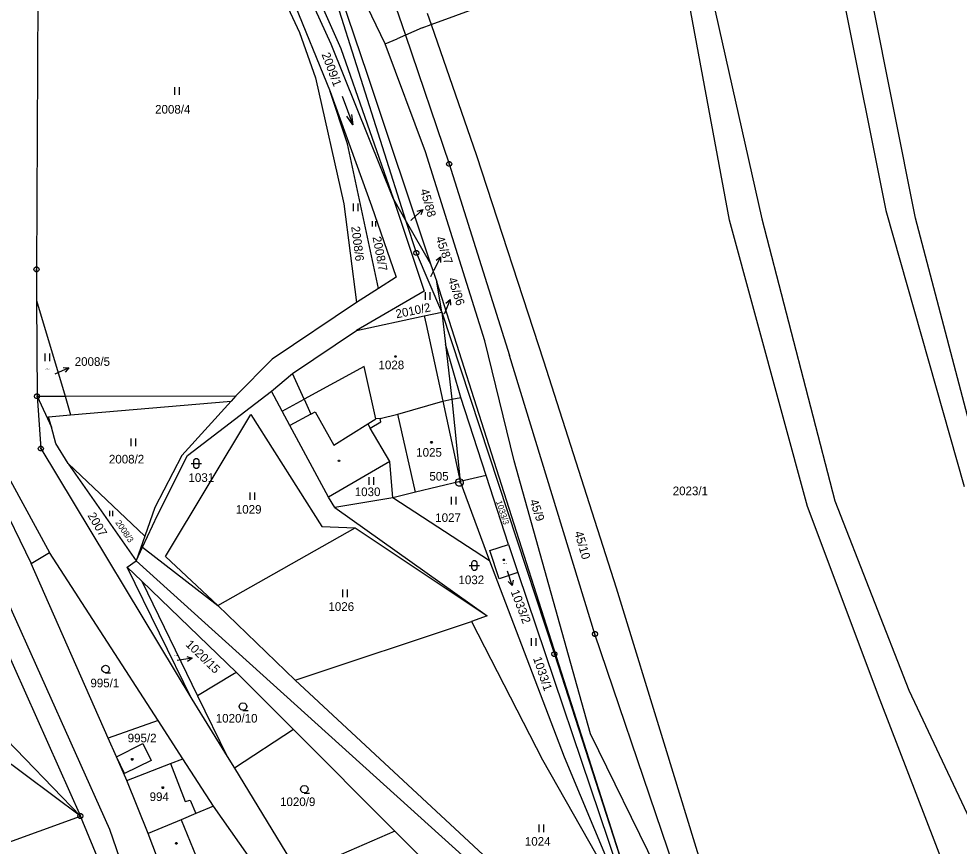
# Model space of a CAD drawing. Extents: x -609861 to -605046, y -1120287 to -1116307.
# Drawn here: x -607702.6 to -607517.4, y -1118558 to -1118395 of the extents above; entities that cross this region are included whole.
import ezdxf

# ---------------------------------------------------------------- set-up
doc = ezdxf.new("R2010")
doc.units = 0
for name, color, linetype in [('Vrstva 1', 7, 'Continuous'), ('Vrstva 2', 7, 'Continuous'), ('Vrstva 3', 7, 'Continuous'), ('Vrstva 4', 7, 'Continuous'), ('Vrstva 5', 7, 'Continuous'), ('Vrstva 7', 7, 'Continuous'), ('Vrstva 8', 7, 'Continuous')]:
    doc.layers.add(name, color=color, linetype=linetype)

msp = doc.modelspace()

# ---------------------------------------------------------------- linework, layer by layer
at = {"layer": 'Vrstva 1'}
for p, q in [((-607626.28, -1118434.95), (-607655.66, -1118342.38)), ((-607655.66, -1118342.38), (-607633.97, -1118405.89)), ((-607660.12, -1118370.59), (-607647.3, -1118397.68)), ((-607544.1, -1118371.59), (-607531.82, -1118432.76)), ((-607525.99, -1118434.27), (-607538.6, -1118370.99)), ((-607641.07, -1118400.03), (-607653.52, -1118372.62)), ((-607630.48, -1118399.97), (-607642.4, -1118375)), ((-607569.78, -1118374.03), (-607556.29, -1118434.42)), ((-607649.03, -1118378.53), (-607639.21, -1118400.88)), ((-607621.4, -1118396.15), (-607573.11, -1118378.35)), ((-607562.64, -1118434.7), (-607573.11, -1118378.35)), ((-607653.54, -1118379.09), (-607641.29, -1118409.31)), ((-607698.86, -1118390.68), (-607699.1, -1118444.38)), ((-607629.03, -1118390.71), (-607626.47, -1118398.24)), ((-607622.19, -1118393.87), (-607621.4, -1118396.15)), ((-607623.15, -1118396.79), (-607626.47, -1118398.24)), ((-607623.15, -1118396.79), (-607621.4, -1118396.15)), ((-607621.4, -1118396.15), (-607612.48, -1118421.94)), ((-607647.3, -1118397.68), (-607644.16, -1118406.63)), ((-607630.48, -1118399.97), (-607628.07, -1118398.93)), ((-607626.47, -1118398.24), (-607628.07, -1118398.93)), ((-607628.81, -1118430.54), (-607641.07, -1118400.03)), ((-607639.21, -1118400.88), (-607628.81, -1118430.54)), ((-607622.51, -1118421.25), (-607630.48, -1118399.97)), ((-607644.16, -1118406.63), (-607638.59, -1118431.48)), ((-607633.97, -1118405.89), (-607621.49, -1118443.27)), ((-607637.87, -1118419.62), (-607641.29, -1118409.31)), ((-607641.29, -1118409.31), (-607633.12, -1118431.84)), ((-607631.75, -1118448.12), (-607637.87, -1118419.62)), ((-607610.85, -1118458.43), (-607622.51, -1118421.25)), ((-607612.48, -1118421.94), (-607599.29, -1118462.39)), ((-607628.81, -1118430.54), (-607626.28, -1118434.95)), ((-607628.81, -1118430.54), (-607622.79, -1118448.7)), ((-607638.59, -1118431.48), (-607636.11, -1118450.91)), ((-607633.12, -1118431.84), (-607628.26, -1118445.89)), ((-607531.82, -1118432.76), (-607516.42, -1118487.17)), ((-607556.29, -1118434.42), (-607541.9, -1118490.01)), ((-607512.94, -1118484.15), (-607525.99, -1118434.27)), ((-607626.28, -1118434.95), (-607621.49, -1118443.27)), ((-607547.31, -1118491.11), (-607562.64, -1118434.7)), ((-607621.49, -1118443.27), (-607620.29, -1118446.85)), ((-607699.1, -1118444.38), (-607699.08, -1118450.52)), ((-607628.26, -1118445.89), (-607631.75, -1118448.12)), ((-607579.33, -1118575.18), (-607620.29, -1118446.85)), ((-607619.32, -1118452.8), (-607620.29, -1118446.85)), ((-607631.75, -1118448.12), (-607636.11, -1118450.91)), ((-607622.79, -1118448.7), (-607636.07, -1118456.39)), ((-607699.08, -1118450.52), (-607693.49, -1118469.37)), ((-607699.08, -1118450.52), (-607699, -1118469.38)), ((-607636.11, -1118450.91), (-607652.73, -1118462.05)), ((-607622.74, -1118453.54), (-607619.32, -1118452.8)), ((-607619.32, -1118452.8), (-607618.59, -1118459.11)), ((-607619.32, -1118452.8), (-607597.12, -1118520.18)), ((-607636.07, -1118456.39), (-607622.74, -1118453.54)), ((-607648.72, -1118464.87), (-607636.07, -1118456.39)), ((-607605.03, -1118482.13), (-607610.85, -1118458.43)), ((-607618.59, -1118459.11), (-607617.33, -1118469.97)), ((-607615.57, -1118469.61), (-607618.59, -1118459.11)), ((-607652.73, -1118462.05), (-607659.85, -1118469.32)), ((-607589.13, -1118516.23), (-607605.98, -1118461.36)), ((-607599.29, -1118462.39), (-607584.95, -1118507.14)), ((-607652.86, -1118468.36), (-607648.72, -1118464.87)), ((-607699, -1118469.38), (-607698.26, -1118479.69)), ((-607699, -1118469.38), (-607696.18, -1118475.47)), ((-607693.49, -1118469.37), (-607692.4, -1118473.07)), ((-607669.36, -1118481.06), (-607652.86, -1118468.36)), ((-607659.85, -1118469.32), (-607660.8, -1118470.36)), ((-607650.71, -1118472.33), (-607652.86, -1118468.36)), ((-607610.54, -1118485.02), (-607615.57, -1118469.61)), ((-607692.4, -1118473.07), (-607660.8, -1118470.36)), ((-607660.8, -1118470.36), (-607670.47, -1118481.02)), ((-607627.95, -1118472.9), (-607619.09, -1118470.37)), ((-607619.09, -1118470.37), (-607617.33, -1118469.97)), ((-607617.33, -1118469.97), (-607615.67, -1118486.14)), ((-607696.75, -1118473.44), (-607692.4, -1118473.07)), ((-607696.18, -1118475.47), (-607696.75, -1118473.44)), ((-607673.72, -1118500.93), (-607656.93, -1118472.99)), ((-607656.93, -1118472.99), (-607642.92, -1118495.07)), ((-607649.19, -1118475.14), (-607650.71, -1118472.33)), ((-607631.44, -1118473.75), (-607627.95, -1118472.9)), ((-607641.59, -1118489.23), (-607649.19, -1118475.14)), ((-607633.37, -1118475.65), (-607631.29, -1118474.39)), ((-607631.29, -1118474.39), (-607631.44, -1118473.75)), ((-607695.28, -1118478.68), (-607696.18, -1118475.47)), ((-607629.52, -1118482.26), (-607633.37, -1118475.65)), ((-607692.87, -1118482.62), (-607695.28, -1118478.68)), ((-607698.26, -1118479.69), (-607668.49, -1118529.04)), ((-607706.73, -1118481.6), (-607696.52, -1118500.13)), ((-607692.87, -1118482.62), (-607692.79, -1118482.79)), ((-607677.77, -1118496.92), (-607692.87, -1118482.62)), ((-607670.47, -1118481.02), (-607675.83, -1118491.31)), ((-607675.27, -1118492.79), (-607669.36, -1118481.06)), ((-607629.52, -1118482.26), (-607641.59, -1118489.23)), ((-607628.96, -1118489.4), (-607629.52, -1118482.26)), ((-607590, -1118535.91), (-607605.03, -1118482.13)), ((-607692.79, -1118482.79), (-607679.47, -1118501.83)), ((-607615.67, -1118486.14), (-607624.46, -1118488.3)), ((-607615.67, -1118486.14), (-607609.87, -1118501.79)), ((-607606.15, -1118498.57), (-607610.54, -1118485.02)), ((-607624.46, -1118488.3), (-607628.96, -1118489.4)), ((-607640.37, -1118491.31), (-607641.59, -1118489.23)), ((-607628.96, -1118489.4), (-607640.37, -1118491.31)), ((-607609.87, -1118501.79), (-607628.96, -1118489.4)), ((-607541.9, -1118490.01), (-607527.33, -1118527.31)), ((-607675.83, -1118491.31), (-607677.77, -1118496.92)), ((-607640.37, -1118491.31), (-607610.35, -1118512.61)), ((-607533, -1118529.25), (-607547.31, -1118491.11)), ((-607678.21, -1118499.11), (-607675.27, -1118492.79)), ((-607663.42, -1118510.58), (-607636.37, -1118495.33)), ((-607642.92, -1118495.07), (-607636.37, -1118495.33)), ((-607636.37, -1118495.33), (-607610.35, -1118512.61)), ((-607677.77, -1118496.92), (-607679.47, -1118501.83)), ((-607679.47, -1118501.83), (-607678.21, -1118499.11)), ((-607678.21, -1118499.11), (-607663.42, -1118510.58)), ((-607609.81, -1118499.76), (-607606.15, -1118498.57)), ((-607606.15, -1118498.57), (-607604.34, -1118504.13)), ((-607700.18, -1118502.31), (-607696.52, -1118500.13)), ((-607675.15, -1118533.26), (-607696.52, -1118500.13)), ((-607663.42, -1118510.58), (-607673.72, -1118500.93)), ((-607608, -1118505.32), (-607609.81, -1118499.76)), ((-607684.99, -1118536.74), (-607700.18, -1118502.31)), ((-607681.27, -1118503.06), (-607679.47, -1118501.83)), ((-607678.39, -1118505.83), (-607681.27, -1118503.06)), ((-607668.49, -1118529.04), (-607681.27, -1118503.06)), ((-607679.47, -1118501.83), (-607601.98, -1118571.81)), ((-607609.87, -1118501.79), (-607595.18, -1118540.43)), ((-607604.34, -1118504.13), (-607608, -1118505.32)), ((-607604.34, -1118504.13), (-607581.17, -1118572.76)), ((-607659.75, -1118523.8), (-607678.39, -1118505.83)), ((-607678.39, -1118505.83), (-607667.4, -1118528.39)), ((-607584.95, -1118507.14), (-607575.3, -1118538.49)), ((-607663.42, -1118510.58), (-607648.15, -1118525.32)), ((-607648.15, -1118525.32), (-607613.46, -1118513.76)), ((-607610.35, -1118512.61), (-607613.46, -1118513.76)), ((-607613.46, -1118513.76), (-607599.46, -1118541.04)), ((-607575.95, -1118555.12), (-607589.13, -1118516.23)), ((-607597.12, -1118520.18), (-607579.33, -1118575.18)), ((-607690.47, -1118552.09), (-607730.23, -1118522.38)), ((-607648.52, -1118535.03), (-607659.75, -1118523.8)), ((-607648.15, -1118525.32), (-607599.94, -1118570.1)), ((-607714.8, -1118526.88), (-607690.47, -1118552.09)), ((-607668.49, -1118529.04), (-607661.56, -1118540.38)), ((-607667.4, -1118528.39), (-607661.56, -1118540.38)), ((-607527.33, -1118527.31), (-607507.06, -1118570.36)), ((-607518.39, -1118566.98), (-607533, -1118529.25)), ((-607675.15, -1118533.26), (-607684.99, -1118536.74)), ((-607670.28, -1118540.82), (-607675.15, -1118533.26)), ((-607648.52, -1118535.03), (-607660.15, -1118542.68)), ((-607628.52, -1118555.04), (-607648.52, -1118535.03)), ((-607565.61, -1118585.65), (-607590, -1118535.91)), ((-607683.35, -1118540.39), (-607684.99, -1118536.74)), ((-607575.3, -1118538.49), (-607564.75, -1118572.83)), ((-607681.32, -1118545.06), (-607683.35, -1118540.39)), ((-607681.32, -1118545.06), (-607672.73, -1118541.76)), ((-607672.73, -1118541.76), (-607670.28, -1118540.82)), ((-607664.28, -1118550.12), (-607670.28, -1118540.82)), ((-607661.56, -1118540.38), (-607660.15, -1118542.68)), ((-607599.46, -1118541.04), (-607582.22, -1118571.39)), ((-607595.18, -1118540.43), (-607582.22, -1118571.39)), ((-607660.15, -1118542.68), (-607647.55, -1118563.29)), ((-607677.14, -1118555.55), (-607681.32, -1118545.06)), ((-607664.28, -1118550.12), (-607667.75, -1118551.6)), ((-607653, -1118566.11), (-607664.28, -1118550.12)), ((-607708.42, -1118558.58), (-607690.47, -1118552.09)), ((-607676.23, -1118586.6), (-607690.47, -1118552.09)), ((-607670.62, -1118552.83), (-607677.14, -1118555.55)), ((-607667.75, -1118551.6), (-607670.62, -1118552.83)), ((-607670.62, -1118552.83), (-607667.08, -1118561.49)), ((-607673.61, -1118564.63), (-607677.14, -1118555.55)), ((-607628.52, -1118555.04), (-607647.55, -1118563.29)), ((-607617.91, -1118565.65), (-607628.52, -1118555.04)), ((-607565.61, -1118585.65), (-607575.95, -1118555.12))]:
    msp.add_line(p, q, dxfattribs=at)
for points in [[(-607626.47, -1118398.24), (-607617.84, -1118423.61), (-607605.98, -1118461.36)], [(-607619.32, -1118452.8), (-607624.31, -1118441.14), (-607626.28, -1118434.95)], [(-607717.79, -1118510.56), (-607709.98, -1118508.38), (-607690.47, -1118552.09)]]:
    msp.add_lwpolyline(points, dxfattribs=at)
at = {"layer": 'Vrstva 3'}
for p, q in [((-607671.96, -1118408.47), (-607671.96, -1118409.97)), ((-607670.96, -1118409.97), (-607670.96, -1118408.47)), ((-607638.914, -1118410.278), (-607636.826, -1118415.902)), ((-607636.74, -1118431.4), (-607636.74, -1118432.9)), ((-607635.74, -1118432.9), (-607635.74, -1118431.4)), ((-607633.01, -1118434.91), (-607633.01, -1118435.96)), ((-607632.31, -1118435.96), (-607632.31, -1118434.91)), ((-607622.57, -1118448.86), (-607622.57, -1118450.36)), ((-607621.57, -1118450.36), (-607621.57, -1118448.86)), ((-607697.5, -1118460.96), (-607697.5, -1118462.46)), ((-607696.5, -1118462.46), (-607696.5, -1118460.96)), ((-607680.54, -1118477.68), (-607680.54, -1118479.18)), ((-607679.54, -1118479.18), (-607679.54, -1118477.68)), ((-607633.69, -1118485.35), (-607633.69, -1118486.85)), ((-607632.69, -1118486.85), (-607632.69, -1118485.35)), ((-607657.11, -1118488.31), (-607657.11, -1118489.81)), ((-607656.11, -1118489.81), (-607656.11, -1118488.31)), ((-607617.48, -1118489.22), (-607617.48, -1118490.72)), ((-607616.48, -1118490.72), (-607616.48, -1118489.22)), ((-607684.76, -1118491.98), (-607684.76, -1118493.03)), ((-607684.06, -1118493.03), (-607684.06, -1118491.98)), ((-607638.87, -1118507.46), (-607638.87, -1118508.96)), ((-607637.87, -1118508.96), (-607637.87, -1118507.46)), ((-607601.71, -1118517.07), (-607601.71, -1118518.57)), ((-607600.71, -1118518.57), (-607600.71, -1118517.07)), ((-607600.19, -1118553.73), (-607600.19, -1118555.23)), ((-607599.19, -1118555.23), (-607599.19, -1118553.73))]:
    msp.add_line(p, q, dxfattribs=at)
for points in [[(-607637.053, -1118413.853), (-607636.826, -1118415.902), (-607637.991, -1118414.202)], [(-607668.64, -1118482.62), (-607667.37, -1118482.62), (-607666.64, -1118482.62)], [(-607613.88, -1118502.71), (-607612.61, -1118502.71), (-607611.88, -1118502.71)], [(-607685.5, -1118523.86), (-607685.88, -1118523.76), (-607686.15, -1118523.49), (-607686.25, -1118523.12), (-607686.15, -1118522.75), (-607685.88, -1118522.48), (-607685.51, -1118522.38), (-607685.14, -1118522.48), (-607684.87, -1118522.75), (-607684.77, -1118523.13), (-607684.87, -1118523.51), (-607685.14, -1118523.78), (-607685.52, -1118523.88), (-607684.52, -1118523.88)], [(-607658.44, -1118531.24), (-607658.82, -1118531.14), (-607659.09, -1118530.87), (-607659.19, -1118530.5), (-607659.09, -1118530.13), (-607658.82, -1118529.86), (-607658.45, -1118529.76), (-607658.08, -1118529.86), (-607657.81, -1118530.13), (-607657.71, -1118530.51), (-607657.81, -1118530.89), (-607658.08, -1118531.16), (-607658.46, -1118531.26), (-607657.46, -1118531.26)], [(-607646.35, -1118547.53), (-607646.73, -1118547.43), (-607647, -1118547.16), (-607647.1, -1118546.79), (-607647, -1118546.42), (-607646.73, -1118546.15), (-607646.36, -1118546.05), (-607645.99, -1118546.15), (-607645.72, -1118546.42), (-607645.62, -1118546.8), (-607645.72, -1118547.18), (-607645.99, -1118547.45), (-607646.37, -1118547.55), (-607645.37, -1118547.55)]]:
    msp.add_lwpolyline(points, dxfattribs=at)
for points in [[(-607668.14, -1118482.12), (-607668.04, -1118481.83), (-607667.79, -1118481.65), (-607667.48, -1118481.65), (-607667.23, -1118481.83), (-607667.13, -1118482.12), (-607667.13, -1118483.12), (-607667.23, -1118483.41), (-607667.48, -1118483.59), (-607667.79, -1118483.59), (-607668.04, -1118483.41), (-607668.14, -1118483.12)], [(-607613.38, -1118502.21), (-607613.28, -1118501.92), (-607613.03, -1118501.74), (-607612.72, -1118501.74), (-607612.47, -1118501.92), (-607612.37, -1118502.21), (-607612.37, -1118503.21), (-607612.47, -1118503.5), (-607612.72, -1118503.68), (-607613.03, -1118503.68), (-607613.28, -1118503.5), (-607613.38, -1118503.21)]]:
    msp.add_lwpolyline(points, close=True, dxfattribs=at)
at = {"layer": 'Vrstva 4'}
for p, q in [((-607622.74, -1118453.54), (-607622.36, -1118455.25)), ((-607622.36, -1118455.25), (-607619.09, -1118470.37)), ((-607634.56, -1118463.49), (-607646.39, -1118469.96)), ((-607632.3, -1118473.85), (-607634.56, -1118463.49)), ((-607646.39, -1118469.96), (-607648.72, -1118464.87)), ((-607699, -1118469.38), (-607693.49, -1118469.37)), ((-607693.49, -1118469.37), (-607659.85, -1118469.32)), ((-607617.33, -1118469.97), (-607615.57, -1118469.61)), ((-607715.52, -1118470.76), (-607700.18, -1118502.31)), ((-607650.71, -1118472.33), (-607646.39, -1118469.96)), ((-607646.39, -1118469.96), (-607645.06, -1118472.89)), ((-607619.09, -1118470.37), (-607615.67, -1118486.14)), ((-607645.06, -1118472.89), (-607649.19, -1118475.14)), ((-607645.06, -1118472.89), (-607644.21, -1118472.42)), ((-607644.21, -1118472.42), (-607640.57, -1118479.01)), ((-607624.46, -1118488.3), (-607627.95, -1118472.9)), ((-607640.57, -1118479.01), (-607633.85, -1118474.82)), ((-607633.85, -1118474.82), (-607632.3, -1118473.85)), ((-607633.85, -1118474.82), (-607633.37, -1118475.65)), ((-607631.44, -1118473.75), (-607632.3, -1118473.85)), ((-607610.54, -1118485.02), (-607615.67, -1118486.14)), ((-607705.01, -1118509.37), (-607684.75, -1118554.69)), ((-607660.14, -1118524.02), (-607667.4, -1118528.39)), ((-607659.75, -1118523.8), (-607660.14, -1118524.02)), ((-607683.35, -1118540.39), (-607678.16, -1118537.81)), ((-607678.16, -1118537.81), (-607676.52, -1118541.11)), ((-607681.75, -1118543.73), (-607683.35, -1118540.39)), ((-607676.52, -1118541.11), (-607681.75, -1118543.73)), ((-607672.73, -1118541.76), (-607669.84, -1118549.21)), ((-607669.84, -1118549.21), (-607668.82, -1118548.98)), ((-607668.82, -1118548.98), (-607667.75, -1118551.6)), ((-607684.75, -1118554.69), (-607673.85, -1118585.76))]:
    msp.add_line(p, q, dxfattribs=at)
at = {"layer": 'Vrstva 5'}
for points in [[(-607628.32, -1118461.4), (-607628.23, -1118461.55), (-607628.32, -1118461.7), (-607628.5, -1118461.7), (-607628.59, -1118461.55), (-607628.5, -1118461.4)], [(-607621.24, -1118478.32), (-607621.15, -1118478.47), (-607621.24, -1118478.62), (-607621.42, -1118478.62), (-607621.51, -1118478.47), (-607621.42, -1118478.32)], [(-607639.46, -1118481.94), (-607639.37, -1118482.09), (-607639.46, -1118482.24), (-607639.64, -1118482.24), (-607639.73, -1118482.09), (-607639.64, -1118481.94)], [(-607606.99, -1118501.46), (-607606.9, -1118501.61), (-607606.99, -1118501.76), (-607607.17, -1118501.76), (-607607.26, -1118501.61), (-607607.17, -1118501.46)], [(-607680.18, -1118540.77), (-607680.09, -1118540.92), (-607680.18, -1118541.07), (-607680.36, -1118541.07), (-607680.45, -1118540.92), (-607680.36, -1118540.77)], [(-607674.15, -1118546.35), (-607674.06, -1118546.5), (-607674.15, -1118546.65), (-607674.33, -1118546.65), (-607674.42, -1118546.5), (-607674.33, -1118546.35)], [(-607671.47, -1118557.31), (-607671.38, -1118557.46), (-607671.47, -1118557.61), (-607671.65, -1118557.61), (-607671.74, -1118557.46), (-607671.65, -1118557.31)]]:
    msp.add_lwpolyline(points, close=True, dxfattribs=at)
at = {"layer": 'Vrstva 7'}
for p, q in [((-607623.038, -1118432.605), (-607625.26, -1118434.62)), ((-607625.37, -1118434.72), (-607625.26, -1118434.62)), ((-607619.541, -1118441.895), (-607620.86, -1118444.59)), ((-607621.44, -1118445.77), (-607620.86, -1118444.59)), ((-607617.642, -1118450.294), (-607618.78, -1118453.07)), ((-607618.81, -1118453.14), (-607618.78, -1118453.07)), ((-607692.737, -1118463.796), (-607695.48, -1118465.01)), ((-607605.427, -1118506.688), (-607606.34, -1118503.83)), ((-607668.47, -1118520.997), (-607671.44, -1118521.42))]:
    msp.add_line(p, q, dxfattribs=at)
for points in [[(-607624.114, -1118432.906), (-607623.038, -1118432.605), (-607623.443, -1118433.647)], [(-607620.43, -1118442.574), (-607619.541, -1118441.895), (-607619.532, -1118443.013)], [(-607618.484, -1118451.03), (-607617.642, -1118450.294), (-607617.559, -1118451.409)], [(-607693.853, -1118463.743), (-607692.737, -1118463.796), (-607693.449, -1118464.658)], [(-607605.255, -1118505.583), (-607605.427, -1118506.688), (-607606.207, -1118505.887)], [(-607669.531, -1118520.643), (-607668.47, -1118520.997), (-607669.389, -1118521.633)]]:
    msp.add_lwpolyline(points, dxfattribs=at)
at = {"layer": 'Vrstva 8'}
for p, q in [((-607617.96, -1118423.61), (-607617.72, -1118423.61)), ((-607624.43, -1118441.14), (-607624.19, -1118441.14)), ((-607699.22, -1118444.38), (-607698.98, -1118444.38)), ((-607699.12, -1118469.38), (-607698.88, -1118469.38)), ((-607698.38, -1118479.69), (-607698.14, -1118479.69)), ((-607615.88, -1118486.34), (-607615.78, -1118486.34)), ((-607589.25, -1118516.23), (-607589.01, -1118516.23)), ((-607597.24, -1118520.18), (-607597, -1118520.18)), ((-607690.59, -1118552.09), (-607690.35, -1118552.09))]:
    msp.add_line(p, q, dxfattribs=at)
for points in [[(-607617.69, -1118423.13), (-607617.44, -1118423.31), (-607617.34, -1118423.6), (-607617.44, -1118423.89), (-607617.69, -1118424.07), (-607618, -1118424.07), (-607618.25, -1118423.89), (-607618.35, -1118423.6), (-607618.25, -1118423.31), (-607618, -1118423.13)], [(-607624.16, -1118440.66), (-607623.91, -1118440.84), (-607623.81, -1118441.13), (-607623.91, -1118441.42), (-607624.16, -1118441.6), (-607624.47, -1118441.6), (-607624.72, -1118441.42), (-607624.82, -1118441.13), (-607624.72, -1118440.84), (-607624.47, -1118440.66)], [(-607698.95, -1118443.9), (-607698.7, -1118444.08), (-607698.6, -1118444.37), (-607698.7, -1118444.66), (-607698.95, -1118444.84), (-607699.26, -1118444.84), (-607699.51, -1118444.66), (-607699.61, -1118444.37), (-607699.51, -1118444.08), (-607699.26, -1118443.9)], [(-607698.85, -1118468.9), (-607698.6, -1118469.08), (-607698.5, -1118469.37), (-607698.6, -1118469.66), (-607698.85, -1118469.84), (-607699.16, -1118469.84), (-607699.41, -1118469.66), (-607699.51, -1118469.37), (-607699.41, -1118469.08), (-607699.16, -1118468.9)], [(-607698.11, -1118479.21), (-607697.86, -1118479.39), (-607697.76, -1118479.68), (-607697.86, -1118479.97), (-607698.11, -1118480.15), (-607698.42, -1118480.15), (-607698.67, -1118479.97), (-607698.77, -1118479.68), (-607698.67, -1118479.39), (-607698.42, -1118479.21)], [(-607615.64, -1118485.62), (-607615.3, -1118485.81), (-607615.11, -1118486.15), (-607615.11, -1118486.54), (-607615.3, -1118486.88), (-607615.64, -1118487.07), (-607616.03, -1118487.07), (-607616.37, -1118486.88), (-607616.56, -1118486.54), (-607616.56, -1118486.15), (-607616.37, -1118485.81), (-607616.03, -1118485.62)], [(-607588.98, -1118515.75), (-607588.73, -1118515.93), (-607588.63, -1118516.22), (-607588.73, -1118516.51), (-607588.98, -1118516.69), (-607589.29, -1118516.69), (-607589.54, -1118516.51), (-607589.64, -1118516.22), (-607589.54, -1118515.93), (-607589.29, -1118515.75)], [(-607596.97, -1118519.7), (-607596.72, -1118519.88), (-607596.62, -1118520.17), (-607596.72, -1118520.46), (-607596.97, -1118520.64), (-607597.28, -1118520.64), (-607597.53, -1118520.46), (-607597.63, -1118520.17), (-607597.53, -1118519.88), (-607597.28, -1118519.7)], [(-607690.32, -1118551.61), (-607690.07, -1118551.79), (-607689.97, -1118552.08), (-607690.07, -1118552.37), (-607690.32, -1118552.55), (-607690.63, -1118552.55), (-607690.88, -1118552.37), (-607690.98, -1118552.08), (-607690.88, -1118551.79), (-607690.63, -1118551.61)]]:
    msp.add_lwpolyline(points, close=True, dxfattribs=at)

# ---------------------------------------------------------------- texts
at = {"layer": 'Vrstva 2'}
for s, height, rotation, p in [('2009/1', 1.7, 290.71879, (-607643.006, -1118402.012)), ('2008/6', 1.7, 277.19698, (-607637.14, -1118435.966)), ('2008/7', 1.7, 280.80662, (-607632.945, -1118438.033)), ('2010/2', 1.7, 11.68834, (-607628.188, -1118454.032)), ('1033/3', 1.2, 288.02588, (-607608.634, -1118490.124)), ('45/9', 1.7, 288.88532, (-607602.033, -1118489.995)), ('2007', 1.7, 300.57366, (-607689.119, -1118492.864)), ('2008/3', 1.2, 304.18329, (-607683.636, -1118494.269)), ('45/10', 1.7, 286.19242, (-607593.204, -1118496.208)), ('1033/1', 1.7, 288.88532, (-607601.353, -1118521.022))]:
    msp.add_text(s, height=height, rotation=rotation, dxfattribs=at).set_placement(p)
for s, height, p in [('2008/4', 1.7, (-607675.753, -1118413.69)), ('45/88', 0.1, (-607625.577, -1118434.72)), ('45/87', 0.1, (-607621.644, -1118445.77)), ('45/86', 0.1, (-607619.016, -1118453.14)), ('1028', 1.7, (-607631.757, -1118464.05)), ('2008/5', 0.2, (-607697.382, -1118464.05)), ('2008/2', 1.7, (-607684.853, -1118482.62)), ('1025', 1.7, (-607624.337, -1118481.28)), ('1031', 1.7, (-607669.177, -1118486.25)), ('1030', 1.7, (-607636.437, -1118489.05)), ('2023/1', 1.7, (-607573.823, -1118488.87)), ('1029', 1.7, (-607659.857, -1118492.51)), ('1027', 1.7, (-607620.587, -1118494.14)), ('1033/2', 0.2, (-607607.284, -1118502.42)), ('1032', 1.7, (-607616.007, -1118506.4)), ('1026', 1.7, (-607641.617, -1118511.66)), ('1020/15', 0.2, (-607672.184, -1118520.55)), ('995/1', 1.7, (-607688.493, -1118526.72)), ('1020/10', 1.7, (-607663.807, -1118533.67)), ('995/2', 1.7, (-607681.153, -1118537.56)), ('994', 1.7, (-607676.833, -1118549.12)), ('1020/9', 1.7, (-607651.147, -1118550.12)), ('1024', 1.7, (-607602.937, -1118557.93))]:
    msp.add_text(s, height=height, dxfattribs=at).set_placement(p)
at = {"layer": 'Vrstva 7'}
for s, rotation, p in [('45/88', 285.90594, (-607623.567, -1118428.768)), ('45/87', 289.05721, (-607620.532, -1118438.183)), ('45/86', 288.19777, (-607618.105, -1118446.269)), ('1033/2', 290.71879, (-607605.752, -1118507.864)), ('1020/15', 315.87163, (-607669.86, -1118518.424))]:
    msp.add_text(s, height=1.7, rotation=rotation, dxfattribs=at).set_placement(p)
msp.add_text('2008/5', height=1.7, dxfattribs=at).set_placement((-607691.583, -1118463.39))
at = {"layer": 'Vrstva 8'}
msp.add_text('505', height=1.7, dxfattribs=at).set_placement((-607621.743, -1118485.99))

doc.saveas('drawing.dxf')
